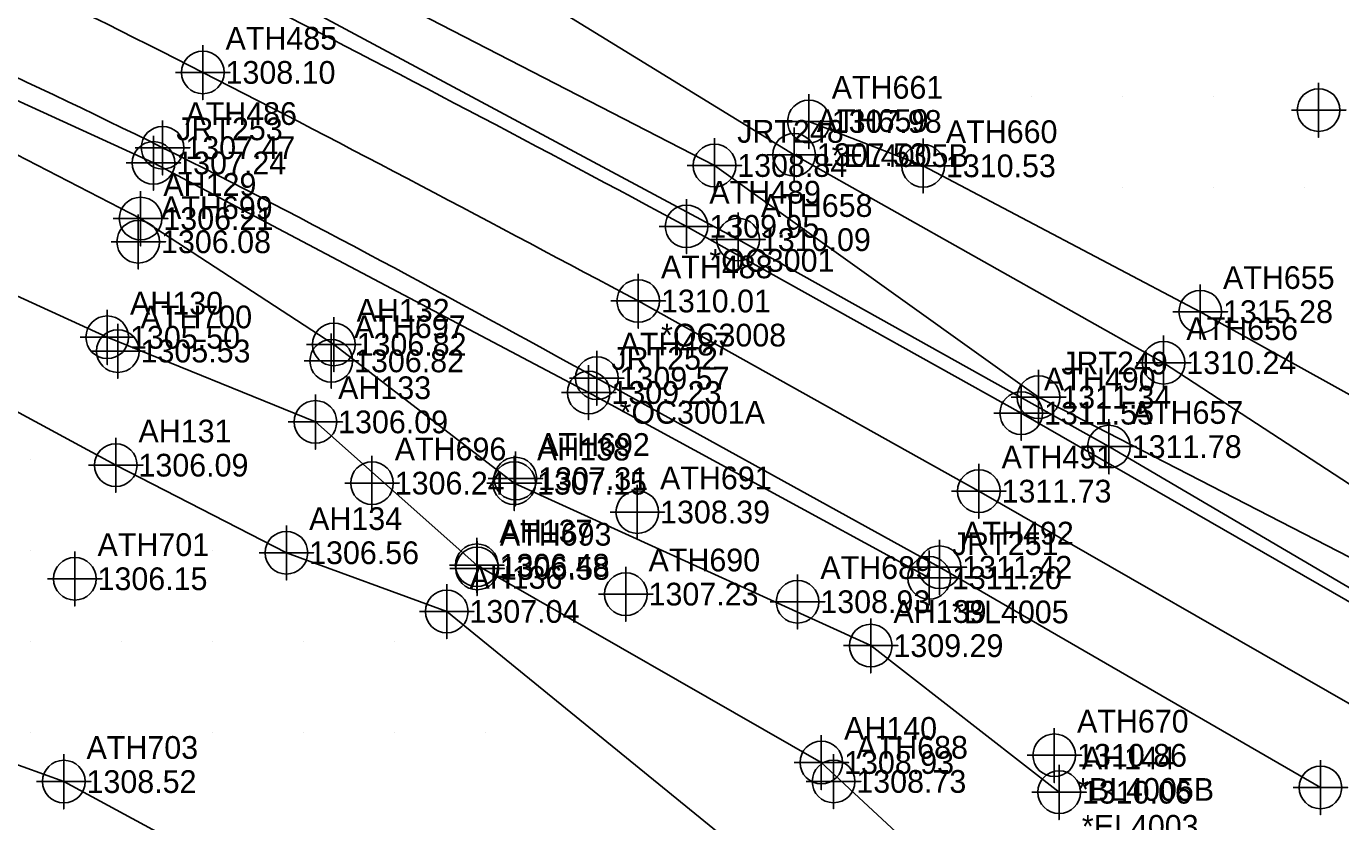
# Model space of a CAD drawing. Extents: x 1234484 to 1235382, y 695050 to 695510.
# Drawn here: x 1235159.5 to 1235304, y 695160.2 to 695247.7 of the extents above; entities that cross this region are included whole.
import ezdxf

# ---------------------------------------------------------------- set-up
doc = ezdxf.new("R2010")
doc.units = 0
for name, color, linetype in [('Exist DTM Breakline', 7, 'Continuous'), ('Exist DTM Breakline Cogo Comment', 7, 'Continuous'), ('Exist DTM Breakline Cogo Elevation', 7, 'Continuous'), ('Exist DTM Breakline Cogo Number', 7, 'Continuous'), ('Exist DTM Breakline Cogo Point CELL', 7, 'Continuous'), ('Exist DTM Breakline Underwater', 7, 'Continuous'), ('Exist DTM Crownline', 7, 'Continuous'), ('Exist DTM Crownline Cogo Comment', 7, 'Continuous'), ('Exist DTM Crownline Cogo Elevation', 7, 'Continuous'), ('Exist DTM Crownline Cogo Number', 7, 'Continuous'), ('Exist DTM Crownline Cogo Point CELL', 7, 'Continuous'), ('Exist DTM Drainline Cogo Comment', 7, 'Continuous'), ('Exist DTM Drainline Cogo Elevation', 7, 'Continuous'), ('Exist DTM Drainline Cogo Number', 7, 'Continuous'), ('Exist DTM Drainline Cogo Point CELL', 7, 'Continuous'), ('Exist DTM QL2 LIDAR Elevation Point', 7, 'Continuous'), ('Exist DTM Regular Point CELL', 7, 'Continuous'), ('Exist DTM Regular Point Cogo Elevation', 7, 'Continuous'), ('Exist DTM Regular Point Cogo Number', 7, 'Continuous'), ('Exist DTM Regular Point Underwater CELL', 7, 'Continuous'), ('Exist DTM Regular Point Underwater Cogo Elevation', 7, 'Continuous'), ('Exist DTM Regular Point Underwater Cogo Number', 7, 'Continuous'), ('Exist Hydro Stream or Body of Water', 7, 'Continuous'), ('Exist Roads EOP', 7, 'Continuous'), ('Exist Roads EOP Cogo Comment', 7, 'Continuous'), ('Exist Roads EOP Cogo Elevation', 7, 'Continuous'), ('Exist Roads EOP Cogo Number', 7, 'Continuous'), ('Exist Roads EOP Cogo Point CELL', 7, 'Continuous')]:
    doc.layers.add(name, color=color, linetype=linetype)

msp = doc.modelspace()

# ---------------------------------------------------------------- linework, layer by layer
at = {"layer": 'Exist DTM Breakline'}
for points in [[(1235319.256, 695177.55), (1235278.534, 695201.47), (1235237.781, 695224.217), (1235188.481, 695250.698), (1235134.96, 695275.849), (1235082.338, 695295.901), (1235034.938, 695310.723), (1234997.435, 695322.999)], [(1235324.566, 695184.553), (1235284.54, 695210.684), (1235243.923, 695233.555), (1235196.6, 695262.635), (1235143.527, 695290.446), (1235093.587, 695315.971)], [(1235094.433, 695303.192), (1235139.249, 695284.24), (1235185.145, 695258.152), (1235235.18, 695232.365), (1235270.796, 695206.904), (1235315.147, 695184.076)], [(1235258.778, 695187.05), (1235221.35, 695207.416), (1235173.519, 695232.644), (1235125.211, 695254.804), (1235075.73, 695275.107), (1235023.735, 695288.012), (1234968.789, 695301.22)], [(1235332.285, 695192.012), (1235288.571, 695216.301), (1235258.111, 695232.33), (1235245.562, 695237.206)], [(1235242.403, 695122.486), (1235188.913, 695150.987), (1235163.662, 695164.651), (1235112.238, 695183.191), (1235055.183, 695204.784), (1235005.3, 695209.27), (1234956.312, 695230.116)]]:
    msp.add_lwpolyline(points, dxfattribs=at)
at = {"layer": 'Exist DTM Breakline Cogo Point CELL'}
for points in [[(1235245.562, 695240.206), (1235245.562, 695234.206), (1235245.562, 695237.206), (1235248.562, 695237.206), (1235242.562, 695237.206)], [(1235243.923, 695236.555), (1235243.923, 695230.555), (1235243.923, 695233.555), (1235246.923, 695233.555), (1235240.923, 695233.555)], [(1235173.519, 695235.644), (1235173.519, 695229.644), (1235173.519, 695232.644), (1235176.519, 695232.644), (1235170.519, 695232.644)], [(1235235.18, 695235.365), (1235235.18, 695229.365), (1235235.18, 695232.365), (1235238.18, 695232.365), (1235232.18, 695232.365)], [(1235258.111, 695235.33), (1235258.111, 695229.33), (1235258.111, 695232.33), (1235261.111, 695232.33), (1235255.111, 695232.33)], [(1235171.852, 695226.987), (1235171.852, 695220.987), (1235171.852, 695223.987), (1235174.852, 695223.987), (1235168.852, 695223.987)], [(1235237.781, 695227.217), (1235237.781, 695221.217), (1235237.781, 695224.217), (1235240.781, 695224.217), (1235234.781, 695224.217)], [(1235288.571, 695219.301), (1235288.571, 695213.301), (1235288.571, 695216.301), (1235291.571, 695216.301), (1235285.571, 695216.301)], [(1235193.066, 695213.891), (1235193.066, 695207.891), (1235193.066, 695210.891), (1235196.066, 695210.891), (1235190.066, 695210.891)], [(1235284.54, 695213.684), (1235284.54, 695207.684), (1235284.54, 695210.684), (1235287.54, 695210.684), (1235281.54, 695210.684)], [(1235221.35, 695210.416), (1235221.35, 695204.416), (1235221.35, 695207.416), (1235224.35, 695207.416), (1235218.35, 695207.416)], [(1235270.796, 695209.904), (1235270.796, 695203.904), (1235270.796, 695206.904), (1235273.796, 695206.904), (1235267.796, 695206.904)], [(1235278.534, 695204.47), (1235278.534, 695198.47), (1235278.534, 695201.47), (1235281.534, 695201.47), (1235275.534, 695201.47)], [(1235213.302, 695200.948), (1235213.302, 695194.948), (1235213.302, 695197.948), (1235216.302, 695197.948), (1235210.302, 695197.948)], [(1235226.698, 695197.275), (1235226.698, 695191.275), (1235226.698, 695194.275), (1235229.698, 695194.275), (1235223.698, 695194.275)], [(1235258.778, 695190.05), (1235258.778, 695184.05), (1235258.778, 695187.05), (1235261.778, 695187.05), (1235255.778, 695187.05)], [(1235244.312, 695187.417), (1235244.312, 695181.417), (1235244.312, 695184.417), (1235247.312, 695184.417), (1235241.312, 695184.417)], [(1235272.528, 695170.541), (1235272.528, 695164.541), (1235272.528, 695167.541), (1235275.528, 695167.541), (1235269.528, 695167.541)], [(1235163.662, 695167.651), (1235163.662, 695161.651), (1235163.662, 695164.651), (1235166.662, 695164.651), (1235160.662, 695164.651)]]:
    msp.add_lwpolyline(points, dxfattribs=at)
for centre in [(1235245.562, 695237.206), (1235173.519, 695232.644), (1235243.923, 695233.555), (1235235.18, 695232.365), (1235258.111, 695232.33), (1235171.852, 695223.987), (1235237.781, 695224.217), (1235288.571, 695216.301), (1235193.066, 695210.891), (1235284.54, 695210.684), (1235221.35, 695207.416), (1235270.796, 695206.904), (1235278.534, 695201.47), (1235213.302, 695197.948), (1235226.698, 695194.275), (1235258.778, 695187.05), (1235244.312, 695184.417), (1235272.528, 695167.541), (1235163.662, 695164.651)]:
    msp.add_circle(centre, 2.344, dxfattribs=at)
at = {"layer": 'Exist DTM Breakline Underwater'}
msp.add_lwpolyline([(1234948.239, 695292.841), (1234952.805, 695292.84), (1234960.83, 695292.864), (1234972.599, 695288.481), (1235023.203, 695275.502), (1235056.399, 695264.585), (1235086.587, 695258.395), (1235121.582, 695234.941), (1235168.445, 695213.485), (1235191.313, 695204.186), (1235209.05, 695188.429), (1235246.922, 695166.749), (1235265.478, 695149.496)], dxfattribs=at)
at = {"layer": 'Exist DTM Crownline'}
msp.add_lwpolyline([(1235226.8, 695217.474), (1235264.229, 695196.574), (1235307.276, 695171.87)], dxfattribs=at)
msp.add_spline([(1234978.534, 695313.159), (1235028.867, 695302.317), (1235079.475, 695286.154), (1235130.202, 695265.942), (1235178.94, 695242.599), (1235226.8, 695217.474)], degree=3, dxfattribs=at)
at = {"layer": 'Exist DTM Crownline Cogo Point CELL'}
for points in [[(1235178.94, 695245.599), (1235178.94, 695239.599), (1235178.94, 695242.599), (1235181.94, 695242.599), (1235175.94, 695242.599)], [(1235226.8, 695220.474), (1235226.8, 695214.474), (1235226.8, 695217.474), (1235229.8, 695217.474), (1235223.8, 695217.474)], [(1235264.229, 695199.574), (1235264.229, 695193.574), (1235264.229, 695196.574), (1235267.229, 695196.574), (1235261.229, 695196.574)]]:
    msp.add_lwpolyline(points, dxfattribs=at)
for centre in [(1235178.94, 695242.599), (1235226.8, 695217.474), (1235264.229, 695196.574)]:
    msp.add_circle(centre, 2.344, dxfattribs=at)
at = {"layer": 'Exist DTM Drainline Cogo Point CELL'}
for points in [[(1235172.108, 695229.531), (1235172.108, 695223.531), (1235172.108, 695226.531), (1235175.108, 695226.531), (1235169.108, 695226.531)], [(1235193.345, 695215.706), (1235193.345, 695209.706), (1235193.345, 695212.706), (1235196.345, 695212.706), (1235190.345, 695212.706)], [(1235169.371, 695202.43), (1235169.371, 695196.43), (1235169.371, 695199.43), (1235172.371, 695199.43), (1235166.371, 695199.43)], [(1235213.169, 695200.447), (1235213.169, 695194.447), (1235213.169, 695197.447), (1235216.169, 695197.447), (1235210.169, 695197.447)], [(1235188.125, 695192.805), (1235188.125, 695186.805), (1235188.125, 695189.805), (1235191.125, 695189.805), (1235185.125, 695189.805)], [(1235205.75, 695186.352), (1235205.75, 695180.352), (1235205.75, 695183.352), (1235208.75, 695183.352), (1235202.75, 695183.352)], [(1235252.346, 695182.593), (1235252.346, 695176.593), (1235252.346, 695179.593), (1235255.346, 695179.593), (1235249.346, 695179.593)], [(1235273.059, 695166.484), (1235273.059, 695160.484), (1235273.059, 695163.484), (1235276.059, 695163.484), (1235270.059, 695163.484)]]:
    msp.add_lwpolyline(points, dxfattribs=at)
for centre in [(1235172.108, 695226.531), (1235193.345, 695212.706), (1235169.371, 695199.43), (1235213.169, 695197.447), (1235188.125, 695189.805), (1235205.75, 695183.352), (1235252.346, 695179.593), (1235273.059, 695163.484)]:
    msp.add_circle(centre, 2.344, dxfattribs=at)
at = {"layer": 'Exist DTM QL2 LIDAR Elevation Point'}
for p, q in [((1235260, 695240), (1235260, 695240)), ((1235270, 695240), (1235270, 695240)), ((1235280, 695240), (1235280, 695240)), ((1235290, 695240), (1235290, 695240)), ((1235300, 695240), (1235300, 695240)), ((1235280, 695230), (1235280, 695230)), ((1235290, 695230), (1235290, 695230)), ((1235300, 695230), (1235300, 695230)), ((1235160, 695200), (1235160, 695200)), ((1235160, 695190), (1235160, 695190)), ((1235170, 695190), (1235170, 695190)), ((1235180, 695190), (1235180, 695190)), ((1235160, 695180), (1235160, 695180)), ((1235170, 695180), (1235170, 695180)), ((1235180, 695180), (1235180, 695180)), ((1235190, 695180), (1235190, 695180)), ((1235200, 695180), (1235200, 695180)), ((1235160, 695170), (1235160, 695170)), ((1235170, 695170), (1235170, 695170)), ((1235180, 695170), (1235180, 695170)), ((1235190, 695170), (1235190, 695170)), ((1235200, 695170), (1235200, 695170)), ((1235210, 695170), (1235210, 695170))]:
    msp.add_line(p, q, dxfattribs=at)
at = {"layer": 'Exist DTM Regular Point CELL'}
for points in [[(1235301.58, 695241.46), (1235301.58, 695235.46), (1235301.58, 695238.46), (1235304.58, 695238.46), (1235298.58, 695238.46)], [(1235164.872, 695189.944), (1235164.872, 695183.944), (1235164.872, 695186.944), (1235167.872, 695186.944), (1235161.872, 695186.944)]]:
    msp.add_lwpolyline(points, dxfattribs=at)
for centre in [(1235301.58, 695238.46), (1235164.872, 695186.944)]:
    msp.add_circle(centre, 2.344, dxfattribs=at)
at = {"layer": 'Exist DTM Regular Point Underwater CELL'}
for points in [[(1235168.445, 695216.485), (1235168.445, 695210.485), (1235168.445, 695213.485), (1235171.445, 695213.485), (1235165.445, 695213.485)], [(1235169.598, 695214.971), (1235169.598, 695208.971), (1235169.598, 695211.971), (1235172.598, 695211.971), (1235166.598, 695211.971)], [(1235191.313, 695207.186), (1235191.313, 695201.186), (1235191.313, 695204.186), (1235194.313, 695204.186), (1235188.313, 695204.186)], [(1235197.537, 695200.455), (1235197.537, 695194.455), (1235197.537, 695197.455), (1235200.537, 695197.455), (1235194.537, 695197.455)], [(1235209.05, 695191.429), (1235209.05, 695185.429), (1235209.05, 695188.429), (1235212.05, 695188.429), (1235206.05, 695188.429)], [(1235209.09, 695191.087), (1235209.09, 695185.087), (1235209.09, 695188.087), (1235212.09, 695188.087), (1235206.09, 695188.087)], [(1235225.432, 695188.256), (1235225.432, 695182.256), (1235225.432, 695185.256), (1235228.432, 695185.256), (1235222.432, 695185.256)], [(1235246.922, 695169.749), (1235246.922, 695163.749), (1235246.922, 695166.749), (1235249.922, 695166.749), (1235243.922, 695166.749)], [(1235248.269, 695167.67), (1235248.269, 695161.67), (1235248.269, 695164.67), (1235251.269, 695164.67), (1235245.269, 695164.67)]]:
    msp.add_lwpolyline(points, dxfattribs=at)
for centre in [(1235168.445, 695213.485), (1235169.598, 695211.971), (1235191.313, 695204.186), (1235197.537, 695197.455), (1235209.05, 695188.429), (1235209.09, 695188.087), (1235225.432, 695185.256), (1235246.922, 695166.749), (1235248.269, 695164.67)]:
    msp.add_circle(centre, 2.344, dxfattribs=at)
at = {"layer": 'Exist Hydro Stream or Body of Water'}
for points in [[(1235024.437, 695280.431), (1235058.02, 695274.707), (1235089.925, 695266.038), (1235123.219, 695251.801), (1235172.108, 695226.531), (1235193.345, 695212.706), (1235213.169, 695197.447), (1235252.346, 695179.593), (1235273.059, 695163.484)], [(1235018.754, 695261.568), (1235053.271, 695252.381), (1235081.661, 695240.144), (1235119.353, 695226.521), (1235169.371, 695199.43), (1235188.125, 695189.805), (1235205.75, 695183.352), (1235242.093, 695153.734), (1235263.468, 695141.323)]]:
    msp.add_lwpolyline(points, dxfattribs=at)
at = {"layer": 'Exist Roads EOP'}
for points in [[(1235232.115, 695225.68), (1235268.895, 695205.143), (1235311.893, 695180.416)], [(1235222.247, 695208.988), (1235259.903, 695188.209), (1235301.775, 695164.014)]]:
    msp.add_lwpolyline(points, dxfattribs=at)
for points in [[(1234989.744, 695321.275), (1235032.632, 695310.758), (1235082.97, 695294.625), (1235134.247, 695274.482), (1235183.928, 695250.955), (1235232.115, 695225.68)], [(1234969.592, 695304.589), (1235025.451, 695292.964), (1235076.313, 695277.193), (1235126.218, 695256.569), (1235174.523, 695234.324), (1235222.247, 695208.988)]]:
    msp.add_spline(points, degree=3, dxfattribs=at)
at = {"layer": 'Exist Roads EOP Cogo Point CELL'}
for points in [[(1235174.523, 695237.324), (1235174.523, 695231.324), (1235174.523, 695234.324), (1235177.523, 695234.324), (1235171.523, 695234.324)], [(1235232.115, 695228.68), (1235232.115, 695222.68), (1235232.115, 695225.68), (1235235.115, 695225.68), (1235229.115, 695225.68)], [(1235222.247, 695211.988), (1235222.247, 695205.988), (1235222.247, 695208.988), (1235225.247, 695208.988), (1235219.247, 695208.988)], [(1235268.895, 695208.143), (1235268.895, 695202.143), (1235268.895, 695205.143), (1235271.895, 695205.143), (1235265.895, 695205.143)], [(1235259.903, 695191.209), (1235259.903, 695185.209), (1235259.903, 695188.209), (1235262.903, 695188.209), (1235256.903, 695188.209)], [(1235301.775, 695167.014), (1235301.775, 695161.014), (1235301.775, 695164.014), (1235304.775, 695164.014), (1235298.775, 695164.014)]]:
    msp.add_lwpolyline(points, dxfattribs=at)
for centre in [(1235174.523, 695234.324), (1235232.115, 695225.68), (1235222.247, 695208.988), (1235268.895, 695205.143), (1235259.903, 695188.209), (1235301.775, 695164.014)]:
    msp.add_circle(centre, 2.344, dxfattribs=at)

# ---------------------------------------------------------------- texts
at = {"layer": 'Exist DTM Breakline Cogo Comment'}
for s, p in [('*EL4005B', (1235248.062, 695232.206)), ('*BL4005', (1235261.278, 695182.05)), ('*BL4005B', (1235275.028, 695162.541))]:
    msp.add_text(s, height=2.5, dxfattribs=at).set_placement(p)
at = {"layer": 'Exist DTM Breakline Cogo Elevation'}
for s, p in [('1307.98', (1235248.062, 695235.956)), ('1307.53', (1235246.423, 695232.305)), ('1307.24', (1235176.019, 695231.394)), ('1308.84', (1235237.68, 695231.115)), ('1310.53', (1235260.611, 695231.08)), ('1306.08', (1235174.352, 695222.737)), ('1310.09', (1235240.281, 695222.967)), ('1315.28', (1235291.071, 695215.051)), ('1306.82', (1235195.566, 695209.641)), ('1310.24', (1235287.04, 695209.434)), ('1309.23', (1235223.85, 695206.166)), ('1311.34', (1235273.296, 695205.654)), ('1311.78', (1235281.034, 695200.22)), ('1307.31', (1235215.802, 695196.698)), ('1308.39', (1235229.198, 695193.025)), ('1311.20', (1235261.278, 695185.8)), ('1308.93', (1235246.812, 695183.167)), ('1310.86', (1235275.028, 695166.291)), ('1308.52', (1235166.162, 695163.401))]:
    msp.add_text(s, height=2.5, dxfattribs=at).set_placement(p)
at = {"layer": 'Exist DTM Breakline Cogo Number'}
for s, p in [('ATH661', (1235248.062, 695239.706)), ('JRT253', (1235176.019, 695235.144)), ('ATH659', (1235246.423, 695236.055)), ('JRT248', (1235237.68, 695234.865)), ('ATH660', (1235260.611, 695234.83)), ('ATH699', (1235174.352, 695226.487)), ('ATH658', (1235240.281, 695226.717)), ('ATH655', (1235291.071, 695218.801)), ('ATH697', (1235195.566, 695213.391)), ('ATH656', (1235287.04, 695213.184)), ('JRT252', (1235223.85, 695209.916)), ('JRT249', (1235273.296, 695209.404)), ('ATH657', (1235281.034, 695203.97)), ('ATH692', (1235215.802, 695200.448)), ('ATH691', (1235229.198, 695196.775)), ('JRT251', (1235261.278, 695189.55)), ('ATH689', (1235246.812, 695186.917)), ('ATH670', (1235275.028, 695170.041)), ('ATH703', (1235166.162, 695167.151))]:
    msp.add_text(s, height=2.5, dxfattribs=at).set_placement(p)
at = {"layer": 'Exist DTM Crownline Cogo Comment'}
msp.add_text('*OC3008', height=2.5, dxfattribs=at).set_placement((1235229.3, 695212.474))
at = {"layer": 'Exist DTM Crownline Cogo Elevation'}
for s, p in [('1308.10', (1235181.44, 695241.349)), ('1310.01', (1235229.3, 695216.224)), ('1311.73', (1235266.729, 695195.324))]:
    msp.add_text(s, height=2.5, dxfattribs=at).set_placement(p)
at = {"layer": 'Exist DTM Crownline Cogo Number'}
for s, p in [('ATH485', (1235181.44, 695245.099)), ('ATH488', (1235229.3, 695219.974)), ('ATH491', (1235266.729, 695199.074))]:
    msp.add_text(s, height=2.5, dxfattribs=at).set_placement(p)
at = {"layer": 'Exist DTM Drainline Cogo Comment'}
msp.add_text('*EL4003', height=2.5, dxfattribs=at).set_placement((1235275.559, 695158.484))
at = {"layer": 'Exist DTM Drainline Cogo Elevation'}
for s, p in [('1306.21', (1235174.608, 695225.281)), ('1306.82', (1235195.845, 695211.456)), ('1306.09', (1235171.871, 695198.18)), ('1307.15', (1235215.669, 695196.197)), ('1306.56', (1235190.625, 695188.555)), ('1307.04', (1235208.25, 695182.102)), ('1309.29', (1235254.846, 695178.343)), ('1310.06', (1235275.559, 695162.234))]:
    msp.add_text(s, height=2.5, dxfattribs=at).set_placement(p)
at = {"layer": 'Exist DTM Drainline Cogo Number'}
for s, p in [('AH129', (1235174.608, 695229.031)), ('AH132', (1235195.845, 695215.206)), ('AH131', (1235171.871, 695201.93)), ('AH138', (1235215.669, 695199.947)), ('AH134', (1235190.625, 695192.305)), ('AH136', (1235208.25, 695185.852)), ('AH139', (1235254.846, 695182.093)), ('AH144', (1235275.559, 695165.984))]:
    msp.add_text(s, height=2.5, dxfattribs=at).set_placement(p)
at = {"layer": 'Exist DTM Regular Point Cogo Elevation'}
msp.add_text('1306.15', height=2.5, dxfattribs=at).set_placement((1235167.372, 695185.694))
at = {"layer": 'Exist DTM Regular Point Cogo Number'}
msp.add_text('ATH701', height=2.5, dxfattribs=at).set_placement((1235167.372, 695189.444))
at = {"layer": 'Exist DTM Regular Point Underwater Cogo Elevation'}
for s, p in [('1305.50', (1235170.945, 695212.235)), ('1305.53', (1235172.098, 695210.721)), ('1306.09', (1235193.813, 695202.936)), ('1306.24', (1235200.037, 695196.205)), ('1306.48', (1235211.55, 695187.179)), ('1306.58', (1235211.59, 695186.837)), ('1307.23', (1235227.932, 695184.006)), ('1308.93', (1235249.422, 695165.499)), ('1308.73', (1235250.769, 695163.42))]:
    msp.add_text(s, height=2.5, dxfattribs=at).set_placement(p)
at = {"layer": 'Exist DTM Regular Point Underwater Cogo Number'}
for s, p in [('AH130', (1235170.945, 695215.985)), ('ATH700', (1235172.098, 695214.471)), ('AH133', (1235193.813, 695206.686)), ('ATH696', (1235200.037, 695199.955)), ('AH137', (1235211.55, 695190.929)), ('ATH693', (1235211.59, 695190.587)), ('ATH690', (1235227.932, 695187.756)), ('AH140', (1235249.422, 695169.249)), ('ATH688', (1235250.769, 695167.17))]:
    msp.add_text(s, height=2.5, dxfattribs=at).set_placement(p)
at = {"layer": 'Exist Roads EOP Cogo Comment'}
for s, p in [('*OC3001', (1235234.615, 695220.68)), ('*OC3001A', (1235224.747, 695203.988))]:
    msp.add_text(s, height=2.5, dxfattribs=at).set_placement(p)
at = {"layer": 'Exist Roads EOP Cogo Elevation'}
for s, p in [('1307.47', (1235177.023, 695233.074)), ('1309.95', (1235234.615, 695224.43)), ('1309.57', (1235224.747, 695207.738)), ('1311.55', (1235271.395, 695203.893)), ('1311.42', (1235262.403, 695186.959))]:
    msp.add_text(s, height=2.5, dxfattribs=at).set_placement(p)
at = {"layer": 'Exist Roads EOP Cogo Number'}
for s, p in [('ATH486', (1235177.023, 695236.824)), ('ATH489', (1235234.615, 695228.18)), ('ATH487', (1235224.747, 695211.488)), ('ATH490', (1235271.395, 695207.643)), ('ATH492', (1235262.403, 695190.709))]:
    msp.add_text(s, height=2.5, dxfattribs=at).set_placement(p)

doc.saveas('drawing.dxf')
